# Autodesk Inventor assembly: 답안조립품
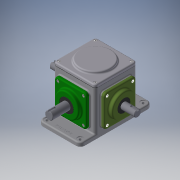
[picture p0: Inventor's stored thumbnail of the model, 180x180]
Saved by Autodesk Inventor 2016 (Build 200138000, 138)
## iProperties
Created: 2019-04
Part Number: 답안조립품
Material: 일반
Document SubType Name: Assembly
Designer: 605-12
Author: 605-12
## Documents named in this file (16)
- C:\Users\605-12\Desktop\390408V1004\답안조립품.iam
- C:\Users\605-12\Desktop\390408V1004\본체.ipt
- C:\Users\605-12\Desktop\390408V1004\베어링 6203.ipt
- C:\Users\605-12\Desktop\390408V1004\볼트 M4.ipt
- C:\Users\605-12\Desktop\390408V1004\서브축.ipt
- C:\Users\605-12\Desktop\390408V1004\서브커버.ipt
- C:\Users\605-12\Desktop\390408V1004\오일 실 17 32 8.ipt
- C:\Users\605-12\Desktop\390408V1004\키 4x4.ipt
- C:\Users\605-12\Desktop\390408V1004\개스킷.ipt
- C:\Users\605-12\Desktop\390408V1004\메인커버.ipt
- C:\Users\605-12\Desktop\390408V1004\상부커버.ipt
- C:\Users\605-12\Desktop\390408V1004\서브베벨기어.ipt
- C:\Users\605-12\Desktop\390408V1004\메인베벨기어.ipt
- C:\Users\605-12\Desktop\390408V1004\메인축.ipt
- C:\Users\605-12\Desktop\390408V1004\베어링 6204.ipt
- C:\Users\605-12\Desktop\390408V1004\오일 실 20 35 8.ipt
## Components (1 placed, 1 different names)
1. 개스킷:1
